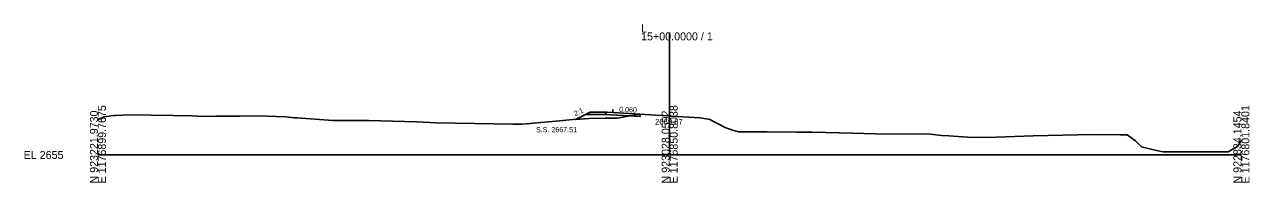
# Model space of a CAD drawing. Extents: x -26 to 1403, y -10 to 9563.
# Drawn here: x -25.7 to 402.8, y 4990.3 to 5045.8 of the extents above; entities that cross this region are included whole.
import ezdxf

# ---------------------------------------------------------------- set-up
doc = ezdxf.new("R2010")
doc.units = 0
for name, color, linetype in [('Exist Cross Section Cell', 7, 'Continuous'), ('Exist XS Center Line Elevation Label', 7, 'Continuous'), ('Exist XS Ground Line', 7, 'Continuous'), ('Prop XS Ditch Slope Text', 7, 'Continuous'), ('Prop XS Dump Level', 7, 'Continuous'), ('Prop XS Earthwork Shape', 7, 'Continuous'), ('Prop XS EOT Tick Mark', 7, 'Continuous'), ('Prop XS Finish Grade', 7, 'Continuous'), ('Prop XS Finish Grade Earthwork', 7, 'Continuous'), ('Prop XS Finish Grade Pavement', 7, 'Continuous'), ('Prop XS Pvmt Edge Slope', 7, 'Continuous'), ('Prop XS SE Text', 7, 'Continuous'), ('Prop XS Shoulder Borrow Shape', 7, 'Continuous'), ('Prop XS SS Elevation Text', 7, 'Continuous'), ('Prop XS Subgrade Earthwork', 7, 'Continuous')]:
    doc.layers.add(name, color=color, linetype=linetype)

msp = doc.modelspace()

# ---------------------------------------------------------------- linework, layer by layer
at = {"layer": 'Exist Cross Section Cell'}
for p, q in [((200, 5000), (200, 5043.04)), ((0, 5000), (200, 5000)), ((200, 5000), (400, 5000))]:
    msp.add_line(p, q, dxfattribs=at)
at = {"layer": 'Exist XS Ground Line'}
for p, q in [((2.17, 5013.36), (5.3, 5013.85)), ((5.3, 5013.85), (6.38, 5013.89)), ((6.38, 5013.89), (10.85, 5014.15)), ((10.85, 5014.15), (18.46, 5013.93)), ((18.46, 5013.93), (26.31, 5013.81)), ((185.39, 5013.6), (189.67, 5014.35)), ((189.67, 5014.35), (195, 5013.98)), ((195, 5013.98), (199.57, 5013.7)), ((0, 5012.5), (0.39, 5012.56)), ((0.39, 5012.56), (2.17, 5013.36)), ((26.31, 5013.81), (32.97, 5013.71)), ((32.97, 5013.71), (34.95, 5013.64)), ((34.95, 5013.64), (38.05, 5013.53)), ((38.05, 5013.53), (41.47, 5013.64)), ((41.47, 5013.64), (47.53, 5013.6)), ((47.53, 5013.6), (49.68, 5013.62)), ((49.68, 5013.62), (55.95, 5013.73)), ((55.95, 5013.73), (65.57, 5013.38)), ((65.57, 5013.38), (68.75, 5013.07)), ((68.75, 5013.07), (69.65, 5013)), ((69.65, 5013), (82.17, 5012.11)), ((82.17, 5012.11), (83.02, 5012.07)), ((83.02, 5012.07), (94.65, 5012.1)), ((94.65, 5012.1), (111.38, 5011.62)), ((111.38, 5011.62), (118.38, 5011.33)), ((118.38, 5011.33), (145.13, 5010.79)), ((145.13, 5010.79), (147.55, 5010.79)), ((147.55, 5010.79), (148.39, 5010.84)), ((148.39, 5010.84), (151.16, 5011.08)), ((151.16, 5011.08), (156.21, 5011.48)), ((156.21, 5011.48), (160.35, 5011.86)), ((160.35, 5011.86), (166.13, 5012.46)), ((166.13, 5012.46), (171.87, 5012.75)), ((171.87, 5012.75), (177.38, 5012.89)), ((177.38, 5012.89), (179.52, 5012.9)), ((179.52, 5012.9), (181.69, 5012.89)), ((181.69, 5012.89), (183.6, 5013.28)), ((183.6, 5013.28), (185.39, 5013.6)), ((199.57, 5013.7), (200, 5013.67)), ((200, 5013.67), (204.69, 5013.39)), ((204.69, 5013.39), (210.57, 5013.07)), ((210.57, 5013.07), (212.89, 5012.64)), ((212.89, 5012.64), (214.07, 5012.43)), ((214.07, 5012.43), (216.09, 5011.35)), ((216.09, 5011.35), (216.98, 5010.9)), ((216.98, 5010.9), (219.38, 5009.65)), ((219.38, 5009.65), (221.63, 5008.86)), ((221.63, 5008.86), (224.11, 5008.15)), ((224.11, 5008.15), (234.11, 5008.14)), ((234.11, 5008.14), (244.53, 5008.06)), ((244.53, 5008.06), (249.81, 5008.02)), ((249.81, 5008.02), (264.04, 5007.71)), ((264.04, 5007.71), (271.88, 5007.39)), ((271.88, 5007.39), (275.95, 5007.3)), ((275.95, 5007.3), (286.41, 5007.39)), ((286.41, 5007.39), (291.16, 5007.32)), ((291.16, 5007.32), (295.26, 5006.86)), ((295.26, 5006.86), (297.65, 5006.67)), ((297.65, 5006.67), (305.79, 5006.08)), ((305.79, 5006.08), (314.26, 5006.31)), ((314.26, 5006.31), (327.21, 5006.77)), ((327.21, 5006.77), (332.45, 5006.83)), ((332.45, 5006.83), (347.83, 5007.15)), ((347.83, 5007.15), (357.6, 5007.1)), ((357.6, 5007.1), (360.03, 5007.12)), ((360.03, 5007.12), (362.95, 5004.96)), ((362.95, 5004.96), (365.03, 5002.9)), ((365.03, 5002.9), (370.32, 5001.52)), ((370.32, 5001.52), (372.61, 5001.05)), ((372.61, 5001.05), (381.8, 5001.05)), ((381.8, 5001.05), (395.41, 5001.05)), ((395.41, 5001.05), (397.83, 5002.53)), ((397.83, 5002.53), (398.61, 5002.92)), ((398.61, 5002.92), (399.17, 5003.87)), ((399.17, 5003.87), (400, 5005.2))]:
    msp.add_line(p, q, dxfattribs=at)
at = {"layer": 'Prop XS Dump Level'}
msp.add_line((189.67, 5014.35), (180.16, 5014.92), dxfattribs=at)
at = {"layer": 'Prop XS Earthwork Shape'}
for p, q in [((167.1, 5012.51), (170.51, 5014.21)), ((170.51, 5014.21), (174.37, 5014.25)), ((174.37, 5014.25), (177.37, 5014.25)), ((177.37, 5014.25), (186.11, 5013.73)), ((171.87, 5012.75), (167.1, 5012.51)), ((177.38, 5012.89), (171.87, 5012.75)), ((179.52, 5012.9), (177.38, 5012.89)), ((181.69, 5012.89), (179.52, 5012.9)), ((183.6, 5013.28), (181.69, 5012.89)), ((185.39, 5013.6), (183.6, 5013.28)), ((186.11, 5013.73), (185.39, 5013.6))]:
    msp.add_line(p, q, dxfattribs=at)
msp.add_lwpolyline([(186.11, 5013.73), (189.67, 5014.35), (189.67, 5013.51)], close=True, dxfattribs=at)
at = {"layer": 'Prop XS EOT Tick Mark'}
msp.add_line((180.16, 5014.92), (180.16, 5015.92), dxfattribs=at)
at = {"layer": 'Prop XS Finish Grade'}
msp.add_line((178.16, 5015.04), (176.59, 5015.04), dxfattribs=at)
at = {"layer": 'Prop XS Finish Grade Earthwork'}
for p, q in [((172.16, 5015.04), (167.1, 5012.51)), ((176.59, 5015.04), (172.16, 5015.04))]:
    msp.add_line(p, q, dxfattribs=at)
at = {"layer": 'Prop XS Finish Grade Pavement'}
msp.add_line((189.67, 5014.35), (178.16, 5015.04), dxfattribs=at)
at = {"layer": 'Prop XS Pvmt Edge Slope'}
msp.add_line((178.16, 5015.04), (177.37, 5014.25), dxfattribs=at)
at = {"layer": 'Prop XS Shoulder Borrow Shape'}
for p, q in [((172.16, 5015.04), (170.51, 5014.21)), ((170.51, 5014.21), (174.37, 5014.25)), ((176.59, 5015.04), (172.16, 5015.04)), ((174.37, 5014.25), (177.37, 5014.25)), ((178.16, 5015.04), (176.59, 5015.04)), ((177.37, 5014.25), (178.16, 5015.04))]:
    msp.add_line(p, q, dxfattribs=at)
at = {"layer": 'Prop XS Subgrade Earthwork'}
for p, q in [((174.37, 5014.25), (170.51, 5014.21)), ((177.37, 5014.25), (174.37, 5014.25)), ((189.67, 5013.51), (177.37, 5014.25)), ((189.67, 5013.51), (189.67, 5014.35))]:
    msp.add_line(p, q, dxfattribs=at)

# ---------------------------------------------------------------- texts
at = {"layer": 'Exist Cross Section Cell'}
for s, p in [('L', (190, 5043.04)), ('15+00.0000 / 1', (190, 5040.24)), ('EL 2655', (-26, 4998.6))]:
    msp.add_text(s, height=2.8, dxfattribs=at).set_placement(p)
for s, p in [('N 923221.9730', (0, 4990)), ('E 1176899.7675', (2.8, 4990)), ('N 923028.0592', (200, 4990)), ('E 1176850.8038', (202.8, 4990)), ('N 922834.1454', (400, 4990)), ('E 1176801.8401', (402.8, 4990))]:
    msp.add_text(s, height=2.8, rotation=90, dxfattribs=at).set_placement(p)
at = {"layer": 'Exist XS Center Line Elevation Label'}
msp.add_text('2668.67', height=2, dxfattribs=at).set_placement((194.91, 5010.67))
at = {"layer": 'Prop XS Ditch Slope Text'}
msp.add_text('2:1', height=1.8, rotation=25.836, dxfattribs=at).set_placement((166.96, 5013.58))
at = {"layer": 'Prop XS Dump Level'}
for s, height, p in [('Case1', 0.04, (172.16, 5014.54)), ('Eop', 0.3, (189.67, 5014))]:
    msp.add_text(s, height=height, dxfattribs=at).set_placement(p)
at = {"layer": 'Prop XS SE Text'}
msp.add_text('0.060', height=1.8, rotation=357.6526, dxfattribs=at).set_placement((182.3, 5015.15))
at = {"layer": 'Prop XS SS Elevation Text'}
msp.add_text('S.S. 2667.51', height=1.8, dxfattribs=at).set_placement((153.23, 5008))

doc.saveas('drawing.dxf')
